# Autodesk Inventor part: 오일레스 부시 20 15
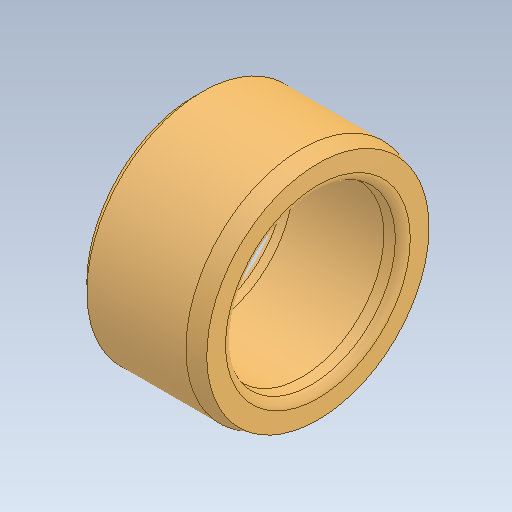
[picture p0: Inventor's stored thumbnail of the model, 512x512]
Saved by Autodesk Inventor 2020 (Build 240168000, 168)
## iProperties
Created: 2024-08
Part Number: 오일레스 부시 20 15
Material: 구리, 합금
Document SubType Name: Modeling
Designer: oem
Density: 8.92 g/cm^3
Appearance: 기본값
Author: jhkim
Sending System: Autodesk Inventor 2025
Preprocessor: ST-DEVELOPER v20
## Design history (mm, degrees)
node "오일레스 부시 20 151"
node "솔리드2"
node "솔리드1"
